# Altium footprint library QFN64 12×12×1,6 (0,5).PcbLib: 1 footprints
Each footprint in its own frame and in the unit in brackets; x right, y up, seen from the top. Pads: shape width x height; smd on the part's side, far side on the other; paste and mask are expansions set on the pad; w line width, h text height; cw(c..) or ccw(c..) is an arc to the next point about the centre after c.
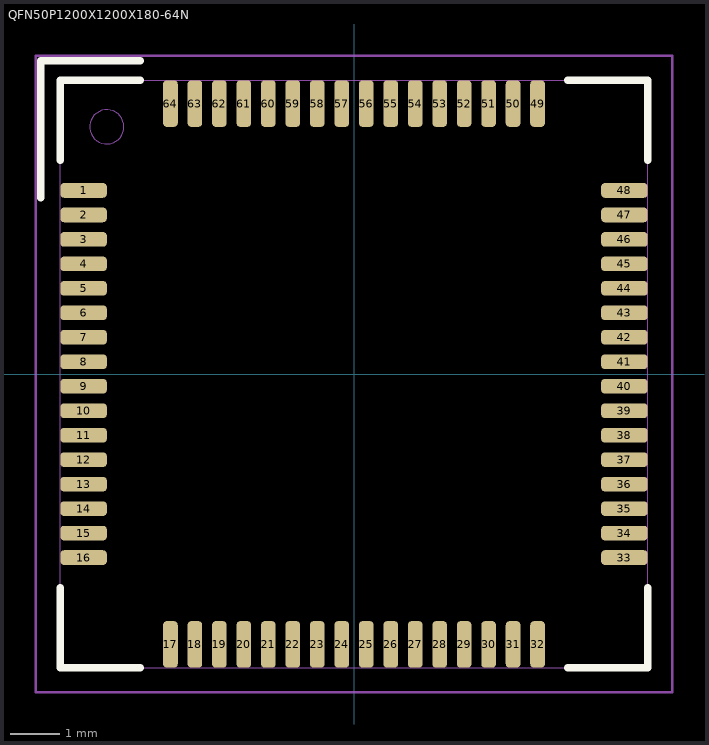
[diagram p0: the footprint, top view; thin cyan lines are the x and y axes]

## QFN50P1200X1200X180-64N [mm] "64-QFN, 0.50 mm pitch, 12.00 X 12.00 X 1.80 mm body"
height 1.8
pads (64):
  rrect50% 0.95x0.3 smd mask+0.05: 1(-5.525,3.75) 2(-5.525,3.25) 3(-5.525,2.75) 4(-5.525,2.25) 5(-5.525,1.75) 6(-5.525,1.25) 7(-5.525,0.75) 8(-5.525,0.25) 9(-5.525,-0.25) 10(-5.525,-0.75) 11(-5.525,-1.25) 12(-5.525,-1.75) 13(-5.525,-2.25) 14(-5.525,-2.75) 15(-5.525,-3.25) 16(-5.525,-3.75) 33(5.525,-3.75) 34(5.525,-3.25) 35(5.525,-2.75) 36(5.525,-2.25) 37(5.525,-1.75) 38(5.525,-1.25) 39(5.525,-0.75) 40(5.525,-0.25) 41(5.525,0.25) 42(5.525,0.75) 43(5.525,1.25) 44(5.525,1.75) 45(5.525,2.25) 46(5.525,2.75) 47(5.525,3.25) 48(5.525,3.75)
  rrect50% 0.3x0.95 smd mask+0.05: 17(-3.75,-5.525) 18(-3.25,-5.525) 19(-2.75,-5.525) 20(-2.25,-5.525) 21(-1.75,-5.525) 22(-1.25,-5.525) 23(-0.75,-5.525) 24(-0.25,-5.525) 25(0.25,-5.525) 26(0.75,-5.525) 27(1.25,-5.525) 28(1.75,-5.525) 29(2.25,-5.525) 30(2.75,-5.525) 31(3.25,-5.525) 32(3.75,-5.525) 49(3.75,5.525) 50(3.25,5.525) 51(2.75,5.525) 52(2.25,5.525) 53(1.75,5.525) 54(1.25,5.525) 55(0.75,5.525) 56(0.25,5.525) 57(-0.25,5.525) 58(-0.75,5.525) 59(-1.25,5.525) 60(-1.75,5.525) 61(-2.25,5.525) 62(-2.75,5.525) 63(-3.25,5.525) 64(-3.75,5.525)
Top Overlay:
  lines w0.15: -6.4,3.6 -6.4,6.4 -4.366,6.4 ; -6,-4.366 -6,-6 -4.366,-6 ; -6,4.365 -6,6 -4.366,6 ; 4.365,-6 6,-6 6,-4.365 ; 4.365,6 6,6 6,4.365
Top Assembly:
  circle w0: c-5.05,5.05 r0.35
  lines w0: -6,-6 -6,6 6,6 6,-6 -6,-6
  text ".Designator" at -2.621,-0.355 h1.52
Top Courtyard:
  lines w0.05: -6.5,-6.5 -6.5,6.5 6.5,6.5 6.5,-6.5 -6.5,-6.5
3D body "QFN50P1200X1200X160-64.STEP": height 1.59, standoff 0, extent -6,-6 6,6
3D body "QFN50P1200X1200X160-64.STEP": height 1.59, standoff 0, extent -6,-6 6,6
